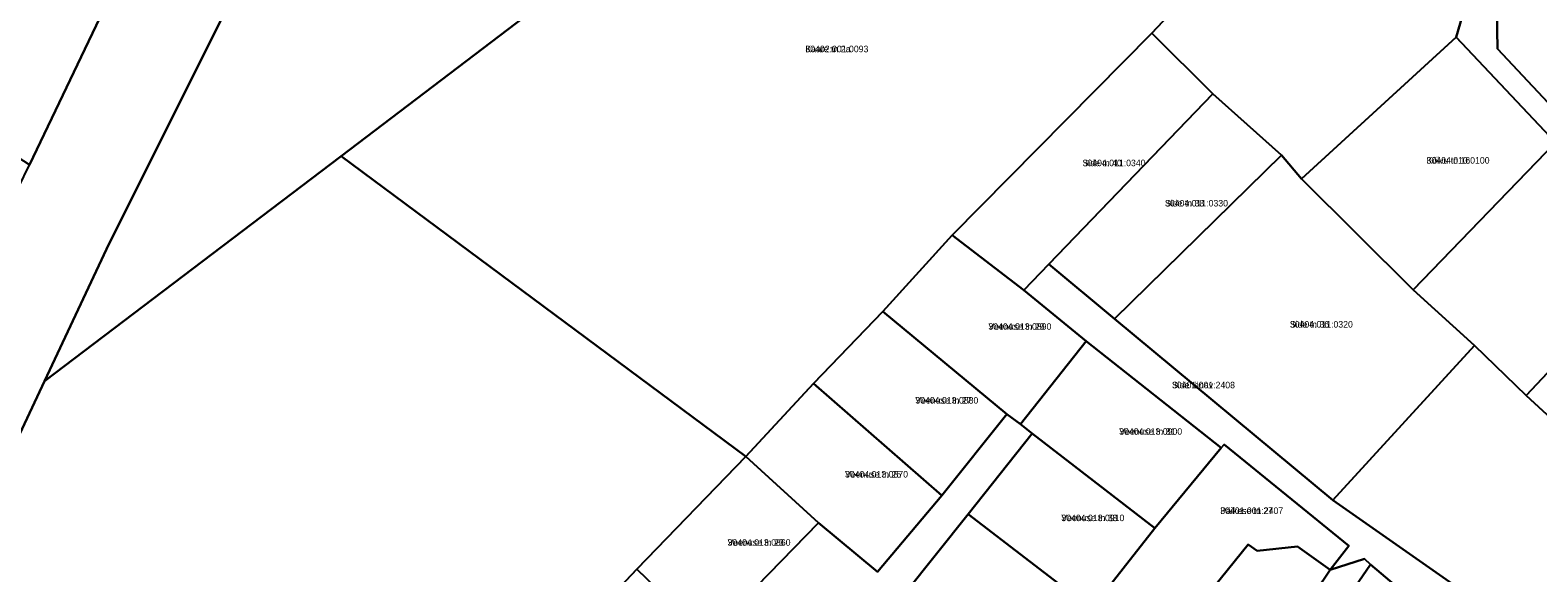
# Model space of a CAD drawing. Extents: x 542681 to 554572, y 6566489 to 6580482.
# Drawn here: x 543606.8 to 543954, y 6576155.9 to 6576281 of the extents above; entities that cross this region are included whole.
import ezdxf

# ---------------------------------------------------------------- set-up
doc = ezdxf.new("R2010")
doc.units = 0
for name, color, linetype in [('L_AADRESS', 7, 'Continuous'), ('PIIR', 7, 'Continuous'), ('TUNNUS', 7, 'Continuous')]:
    doc.layers.add(name, color=color, linetype=linetype)

msp = doc.modelspace()

# ---------------------------------------------------------------- linework, layer by layer
at = {"layer": 'PIIR'}
for points in [[(543758.49, 6576501.47), (543789.73, 6576517.51), (543854.56, 6576498.28), (543909.25, 6576490.8), (543946.22, 6576494.37), (544007.14, 6576508.85), (544074.8, 6576547.93), (544085.24, 6576538.48), (543870.87, 6576403.95), (543856.61, 6576424), (543829.53, 6576408.62), (543810.38, 6576393.03), (543832.23, 6576369.07), (543678.38, 6576251.99), (543610.08, 6576200.08), (543624.99, 6576231.86), (543740.67, 6576463.36)], [(543935.19, 6576279.37), (543936.66, 6576284.38), (543977.09, 6576325.95), (544011.69, 6576361.81), (544046.36, 6576397.94), (544080.52, 6576434.57), (544094.74, 6576449.9), (544109.18, 6576451), (544158.24, 6576416.83), (544207.76, 6576388.65), (544205.21, 6576384.66), (544162.11, 6576408.88), (544149.12, 6576405.45), (544131.72, 6576385.2), (544097.11, 6576350.22), (544062.02, 6576314.43), (544028.25, 6576277.71), (543994.05, 6576241.05), (543983.17, 6576230.7), (543958.09, 6576255.13)], [(543944.58, 6576285.35), (543944.69, 6576276.68), (543960.96, 6576259.37), (543979.61, 6576241.04), (543986.9, 6576241.11), (544024.44, 6576281.04), (544058.69, 6576317.5), (544093.45, 6576353.49), (544128.42, 6576389.19), (544142.76, 6576405.7), (544141.23, 6576422.59), (544109.08, 6576444.98), (544096.12, 6576443.98), (544084.05, 6576431.14), (544049.76, 6576394.71), (544015.25, 6576358.69), (543980.53, 6576322.51)], [(543832.23, 6576369.07), (543889.71, 6576306.51), (543865.14, 6576280.28), (543819.15, 6576233.75), (543803.12, 6576216.14), (543787.17, 6576199.61), (543771.59, 6576182.76), (543678.38, 6576251.99)], [(543591.9, 6576332.78), (543633.91, 6576307.07), (543606.64, 6576249.99), (543557.43, 6576281.74)], [(543865.14, 6576280.28), (543889.71, 6576306.51), (543905.34, 6576323.31), (543914.84, 6576305.8), (543936.66, 6576284.38), (543935.19, 6576279.37), (543899.57, 6576246.77), (543894.94, 6576252.19), (543879.16, 6576266.32)], [(543944.69, 6576276.68), (543944.58, 6576285.35), (543980.53, 6576322.51), (544001.76, 6576302.04), (543960.96, 6576259.37)], [(543835.6, 6576221.08), (543819.15, 6576233.75), (543865.14, 6576280.28), (543879.16, 6576266.32), (543841.35, 6576227.09)], [(543899.57, 6576246.77), (543935.19, 6576279.37), (543958.09, 6576255.13), (543925.27, 6576221.13)], [(543841.35, 6576227.09), (543879.16, 6576266.32), (543894.94, 6576252.19), (543856.53, 6576214.44)], [(543925.27, 6576221.13), (543958.09, 6576255.13), (543983.17, 6576230.7), (543951.32, 6576196.79), (543939.43, 6576208.34)], [(543610.08, 6576200.08), (543678.38, 6576251.99), (543771.59, 6576182.76), (543746.47, 6576156.82), (543720.94, 6576129.63), (543717.45, 6576126.42), (543695.26, 6576105.01), (543680.88, 6576090.14), (543666.51, 6576074.33), (543651.27, 6576057.86), (543637.1, 6576042.64), (543622.09, 6576026.97), (543551.63, 6576075.36)], [(543894.94, 6576252.19), (543899.57, 6576246.77), (543925.27, 6576221.13), (543939.43, 6576208.34), (543906.78, 6576172.72), (543856.53, 6576214.44)], [(543951.32, 6576196.79), (543983.17, 6576230.7), (543994.05, 6576241.05), (544006.55, 6576227.81), (544015.62, 6576220.65), (544010.73, 6576215.34), (543996.3, 6576200.53), (543973.39, 6576176.45)], [(543831.7, 6576192.53), (543803.12, 6576216.14), (543819.15, 6576233.75), (543835.6, 6576221.08), (543850, 6576209.33), (543834.85, 6576190.18)], [(543831.7, 6576192.53), (543816.74, 6576173.76), (543787.17, 6576199.61), (543803.12, 6576216.14)], [(543834.85, 6576190.18), (543850, 6576209.33), (543881.07, 6576184.76), (543865.8, 6576166.2), (543837.56, 6576188.04)], [(543939.43, 6576208.34), (543951.32, 6576196.79), (543973.39, 6576176.45), (543996.3, 6576200.53), (544043.16, 6576166.01), (544009.15, 6576119.22), (543984.31, 6576118.38), (543906.78, 6576172.72)], [(543771.59, 6576182.76), (543787.17, 6576199.61), (543816.74, 6576173.76), (543801.9, 6576156.2), (543788.33, 6576167.45)], [(543837.56, 6576188.04), (543865.8, 6576166.2), (543851.24, 6576147.66), (543822.78, 6576169.45)], [(543881.07, 6576184.76), (543881.73, 6576185.54), (543910.47, 6576162.14), (543906.21, 6576156.61), (543898.67, 6576161.98), (543889.37, 6576160.99), (543887.26, 6576162.45), (543865.62, 6576135.66), (543851.24, 6576147.66), (543865.8, 6576166.2)], [(543746.47, 6576156.82), (543771.59, 6576182.76), (543788.33, 6576167.45), (543762.71, 6576141.11)], [(543822.78, 6576169.45), (543851.24, 6576147.66), (543835.23, 6576129.22), (543808.25, 6576151.17)], [(543887.26, 6576162.45), (543889.37, 6576160.99), (543898.67, 6576161.98), (543906.21, 6576156.61), (543882.6, 6576121.55), (543865.62, 6576135.66)], [(543746.47, 6576156.82), (543762.71, 6576141.11), (543736.97, 6576114.33), (543720.94, 6576129.63)], [(543915.46, 6576157.88), (543946.49, 6576131.63), (543933.19, 6576111.32), (543900.63, 6576136.29)]]:
    msp.add_lwpolyline(points, close=True, dxfattribs=at)
for points in [[(543740.67, 6576463.36), (543624.99, 6576231.86), (543610.08, 6576200.08), (543551.63, 6576075.36), (543550.03, 6576072.1), (543511.86, 6576025.82), (543496.84, 6576048.42), (543563.51, 6576161.2), (543606.64, 6576249.99), (543633.91, 6576307.07)], [(543980.11, 6576110.56), (543946.49, 6576131.63), (543915.46, 6576157.88), (543914.05, 6576159.16), (543906.21, 6576156.61), (543910.47, 6576162.14), (543881.73, 6576185.54), (543881.07, 6576184.76), (543850, 6576209.33), (543835.6, 6576221.08), (543841.35, 6576227.09), (543856.53, 6576214.44), (543906.78, 6576172.72), (543984.31, 6576118.38)], [(543762.71, 6576141.11), (543788.33, 6576167.45), (543801.9, 6576156.2), (543816.74, 6576173.76), (543831.7, 6576192.53), (543834.85, 6576190.18), (543837.56, 6576188.04), (543822.78, 6576169.45), (543808.25, 6576151.17)], [(543882.6, 6576121.55), (543906.21, 6576156.61), (543914.05, 6576159.16), (543915.46, 6576157.88), (543900.63, 6576136.29)]]:
    msp.add_lwpolyline(points, dxfattribs=at)

# ---------------------------------------------------------------- texts
at = {"layer": 'L_AADRESS'}
for s, p in [('Kaare tn 2a', (543785.32, 6576275.92)), ('Side tn 40', (543849.15, 6576249.65)), ('Kõivu tn 16', (543928.38, 6576250.25)), ('Side tn 38', (543868.14, 6576240.37)), ('Veenuse tn 29', (543827.47, 6576211.96)), ('Side tn 36', (543896.9, 6576212.46)), ('Side tänav', (543869.75, 6576198.47)), ('Veenuse tn 27', (543810.64, 6576194.95)), ('Veenuse tn 31', (543857.59, 6576187.76)), ('Veenuse tn 25', (543794.45, 6576177.9)), ('Päikese tn 27', (543880.86, 6576169.51)), ('Veenuse tn 33', (543844.27, 6576167.85)), ('Veenuse tn 23', (543767.4, 6576162.18))]:
    msp.add_text(s, height=1.5, dxfattribs=at).set_placement(p)
at = {"layer": 'TUNNUS'}
for s, p in [('30402:001:0093', (543785.32, 6576275.92)), ('30404:011:0340', (543849.15, 6576249.65)), ('30404:010:0100', (543928.38, 6576250.25)), ('30404:011:0330', (543868.14, 6576240.37)), ('30404:013:0890', (543827.47, 6576211.96)), ('30404:011:0320', (543896.9, 6576212.46)), ('30401:001:2408', (543869.75, 6576198.47)), ('30404:013:0880', (543810.64, 6576194.95)), ('30404:013:0900', (543857.59, 6576187.76)), ('30404:013:0870', (543794.45, 6576177.9)), ('30401:001:2407', (543880.86, 6576169.51)), ('30404:013:0910', (543844.27, 6576167.85)), ('30404:013:0860', (543767.4, 6576162.18))]:
    msp.add_text(s, height=1.5, dxfattribs=at).set_placement(p)

doc.saveas('drawing.dxf')
